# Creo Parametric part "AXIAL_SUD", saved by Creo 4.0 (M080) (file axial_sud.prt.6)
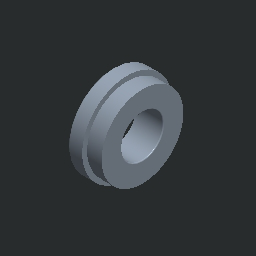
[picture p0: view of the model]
Units: millimeter Kilogram Sec (mmKs); MM, KILOGRAM, SECS
Materials in the file: OCEL_N

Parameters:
  MFG_WP_MATERIAL = "RO7"
  NAZOV = "AXIAL_SUD"
  PTC_MATERIAL_NAME = "OCEL_N"

Other parameters: HMOTNOST, HUSTOTA, D7, D8

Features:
  1. round

Named dimensions: velke_D1, velke_D, velke_H

Layers: 1, 2, 3, 4, 5, 6, 7, 8, 9, 10, 11, 12, 13, 14, 15, 16, 17, 18, 19, 20, 21, 22, 23, 24, 25, 26, 27, 28, 29, 30, 31, 32

Family table entries: GENERIC, LOZISKO_29412, AXIAL_SUD, value(d_val), 2/E, 2/V, 2/4, value(i_val), LOZISKO_29413, AXIAL_SUD, 2/`, 2/5, LOZISKO_29414, AXIAL_SUD, 2/H, 2/7, LOZISKO_29415, AXIAL_SUD, 2/d, 2/H, 2/8, LOZISKO_29416, AXIAL_SUD, !/T, 2/K, 2/], 2/:, LOZISKO_29417, AXIAL_SUD, 2/M, 2/<, LOZISKO_29418, AXIAL_SUD, 2/N, 2/=, LOZISKO_29420, AXIAL_SUD, !/Y, 2/P, 2/@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

Surfaces: 10 cylinder, 5 plane, 4 torus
